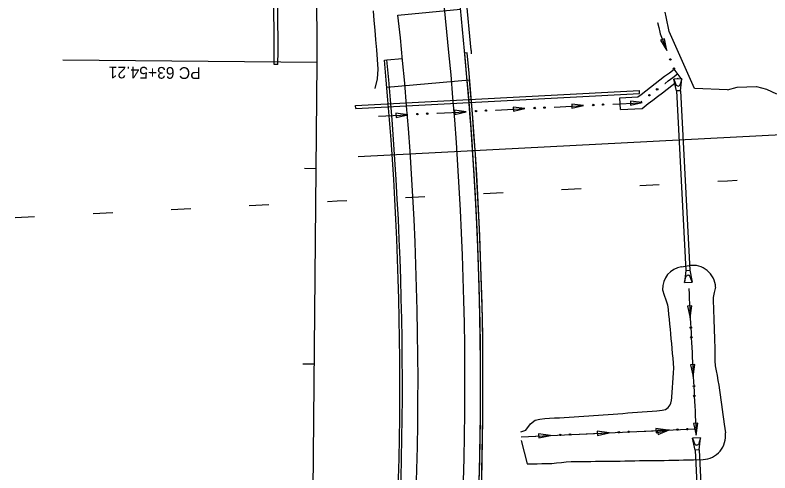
# Model space of a CAD drawing. Extents: x 1304554 to 1314558, y 2088110 to 2090513.
# Drawn here: x 1313845.5 to 1314231.7, y 2089262.8 to 2089497.1 of the extents above; entities that cross this region are included whole.
import ezdxf

# ---------------------------------------------------------------- set-up
doc = ezdxf.new("R2010")
doc.units = 0
for name, color, linetype in [('B-Sub-Retaining Wall', 7, 'Continuous'), ('MOT_Barrier Wall Stage 3', 7, 'Continuous'), ('R_Bridge', 7, 'Continuous'), ('R_Conc Ditch Paving', 7, 'Continuous'), ('R_Drainage', 7, 'Continuous'), ('R_Guardrail', 7, 'Continuous'), ('R_Horz Alg', 7, 'Continuous'), ('R_Horz Alg Annot', 7, 'Continuous'), ('R_Horz Alg Stationing', 7, 'Continuous'), ('R_Proposed Const Limits', 7, 'Continuous'), ('R_Proposed Road', 7, 'Continuous'), ('R_Shld_GR', 7, 'Continuous'), ('R_Shoulder', 7, 'Continuous'), ('R_Special Ditch', 7, 'Continuous'), ('S_Striping', 7, 'Continuous')]:
    doc.layers.add(name, color=color, linetype=linetype)

msp = doc.modelspace()

# ---------------------------------------------------------------- linework, layer by layer
at = {"layer": 'B-Sub-Retaining Wall'}
for p, q in [((1314019.78, 2089450.85), (1314165.01, 2089458.46)), ((1314019.85, 2089449.35), (1314165.09, 2089456.97)), ((1314165.09, 2089456.97), (1314165.01, 2089458.46)), ((1314166.39, 2089452.33), (1314160.35, 2089453.08)), ((1314160.35, 2089453.08), (1314160.45, 2089450.97)), ((1314160.45, 2089450.97), (1314166.39, 2089452.33)), ((1314019.85, 2089449.35), (1314019.78, 2089450.85)), ((1314076.4, 2089447.67), (1314070.35, 2089448.42)), ((1314070.35, 2089448.42), (1314070.46, 2089446.3)), ((1314106.4, 2089449.22), (1314100.35, 2089449.97)), ((1314100.35, 2089449.97), (1314100.46, 2089447.86)), ((1314100.46, 2089447.86), (1314106.4, 2089449.22)), ((1314136.39, 2089450.78), (1314130.35, 2089451.53)), ((1314130.35, 2089451.53), (1314130.46, 2089449.41)), ((1314130.46, 2089449.41), (1314136.39, 2089450.78)), ((1314046.4, 2089446.12), (1314040.35, 2089446.86)), ((1314040.35, 2089446.86), (1314040.46, 2089444.75)), ((1314040.46, 2089444.75), (1314046.4, 2089446.12)), ((1314070.46, 2089446.3), (1314076.4, 2089447.67))]:
    msp.add_line(p, q, dxfattribs=at)
for points in [[(1314178.06, 2089462.16), (1314179.69, 2089463.4), (1314182.1, 2089465.24), (1314184.51, 2089467.05)], [(1314178.03, 2089462.14), (1314178.06, 2089462.16)], [(1314151.41, 2089451.56), (1314165.24, 2089452.27), (1314166.15, 2089452.98)], [(1314091.38, 2089448.45), (1314091.42, 2089448.45)], [(1314091.42, 2089448.45), (1314106.4, 2089449.22)], [(1314121.38, 2089450), (1314121.41, 2089450)], [(1314121.41, 2089450), (1314136.39, 2089450.78)], [(1314151.37, 2089451.56), (1314151.41, 2089451.56)], [(1314031.42, 2089445.34), (1314046.4, 2089446.12)], [(1314061.38, 2089446.89), (1314061.42, 2089446.89)], [(1314061.42, 2089446.89), (1314076.4, 2089447.67)]]:
    msp.add_lwpolyline(points, dxfattribs=at)
for centre in [(1314174.05, 2089459.13), (1314170.09, 2089456.08), (1314081.4, 2089447.97), (1314086.4, 2089448.22), (1314111.39, 2089449.52), (1314116.4, 2089449.78), (1314141.39, 2089451.07), (1314146.39, 2089451.33), (1314051.4, 2089446.41), (1314056.4, 2089446.67)]:
    msp.add_circle(centre, 0.375, dxfattribs=at)
at = {"layer": 'MOT_Barrier Wall Stage 3'}
for p, q in [((1313978.01, 2089471.82), (1313978.03, 2089473.03)), ((1313980.01, 2089471.81), (1313978.01, 2089471.82)), ((1313980.01, 2089471.81), (1313980.02, 2089473.01))]:
    msp.add_line(p, q, dxfattribs=at)
for radius in [1123.92, 1125.92]:
    msp.add_arc((1312854.15, 2089482.84), radius, 359.5, 7, dxfattribs=at)
at = {"layer": 'R_Bridge'}
for p, q in [((1314076.83, 2089477.71), (1314075.59, 2089477.6)), ((1314034.49, 2089474.02), (1314035.74, 2089474.13)), ((1314078.11, 2089463.77), (1314035.77, 2089460.08)), ((1314078.11, 2089463.77), (1314035.77, 2089460.08))]:
    msp.add_line(p, q, dxfattribs=at)
for radius, start, end in [(1782.95, 354.7437, 5.46314), (1784.2, 354.74404, 5.4628), (1741.7, 354.73222, 5.47462), (1742.95, 354.73258, 5.47426), (1782.95, 355.19361, 5.01323), (1784.2, 355.19363, 5.01321)]:
    msp.add_arc((1312300.74, 2089307.86), radius, start, end, dxfattribs=at)
at = {"layer": 'R_Conc Ditch Paving'}
for p, q in [((1314186.31, 2089464.67), (1314182.71, 2089469.45)), ((1314155.02, 2089454.75), (1314164.15, 2089455.23)), ((1314155.33, 2089448.76), (1314155.02, 2089454.75)), ((1314155.33, 2089448.76), (1314166.34, 2089449.33))]:
    msp.add_line(p, q, dxfattribs=at)
for points in [[(1314164.15, 2089455.23), (1314165.81, 2089456.51), (1314168.22, 2089458.38), (1314170.64, 2089460.24), (1314173.05, 2089462.1), (1314175.46, 2089463.95), (1314177.87, 2089465.79), (1314180.29, 2089467.63), (1314182.71, 2089469.45)], [(1314186.08, 2089464.49), (1314186.31, 2089464.67)], [(1314166.34, 2089449.33), (1314169.49, 2089451.77), (1314171.9, 2089453.64), (1314174.3, 2089455.49), (1314176.7, 2089457.34), (1314179.1, 2089459.18), (1314181.51, 2089461.02), (1314183.1, 2089462.23)]]:
    msp.add_lwpolyline(points, dxfattribs=at)
at = {"layer": 'R_Drainage'}
for p, q in [((1314186.64, 2089464.52), (1314182.65, 2089464.31)), ((1314183.96, 2089458.25), (1314182.65, 2089464.31)), ((1314182.65, 2089464.31), (1314183.68, 2089461.56)), ((1314186.64, 2089464.52), (1314185.9, 2089461.68)), ((1314185.96, 2089458.36), (1314186.64, 2089464.52)), ((1314185.96, 2089458.36), (1314183.96, 2089458.25)), ((1314183.96, 2089458.25), (1314188.72, 2089366.38)), ((1314185.96, 2089458.36), (1314190.72, 2089366.48)), ((1314188.72, 2089366.38), (1314188.04, 2089360.21)), ((1314188.04, 2089360.21), (1314188.79, 2089363.06)), ((1314188.72, 2089366.38), (1314190.72, 2089366.48)), ((1314190.72, 2089366.48), (1314192.04, 2089360.42)), ((1314192.04, 2089360.42), (1314191, 2089363.17)), ((1314188.04, 2089360.21), (1314192.04, 2089360.42)), ((1314196.16, 2089280.77), (1314192.17, 2089280.56)), ((1314193.48, 2089274.5), (1314192.17, 2089280.56)), ((1314192.17, 2089280.56), (1314193.2, 2089277.81)), ((1314196.16, 2089280.77), (1314195.42, 2089277.93)), ((1314195.48, 2089274.6), (1314196.16, 2089280.77)), ((1314195.48, 2089274.6), (1314193.48, 2089274.5)), ((1314193.48, 2089274.5), (1314198.5, 2089177.63)), ((1314195.48, 2089274.6), (1314200.5, 2089177.73))]:
    msp.add_line(p, q, dxfattribs=at)
for centre, start, end in [((1314184.77, 2089461.97), 200.4966, 345.4367), ((1314189.91, 2089362.77), 20.4966, 165.4367), ((1314194.29, 2089278.21), 200.4966, 345.4367)]:
    msp.add_arc(centre, 1.17, start, end, dxfattribs=at)
at = {"layer": 'R_Guardrail'}
msp.add_arc((1312300.74, 2089307.86), 1782.95, 5.44344, 5.5, dxfattribs=at)
at = {"layer": 'R_Horz Alg'}
msp.add_line((1313996.9, 2089115.37), (1314000.02, 2089472.84), dxfattribs=at)
msp.add_line((1313996.9, 2089115.37), (1314000.02, 2089472.84), dxfattribs=at)
msp.add_arc((1312854.15, 2089482.84), 1145.92, 359.5, 7, dxfattribs=at)
msp.add_arc((1312854.15, 2089482.84), 1145.92, 359.5, 7, dxfattribs=at)
at = {"layer": 'R_Horz Alg Annot'}
msp.add_lwpolyline([(1314000.02, 2089472.84), (1313870.03, 2089473.97)], dxfattribs=at)
at = {"layer": 'R_Horz Alg Stationing'}
for points in [[(1313993.55, 2089418.69), (1313999.55, 2089418.63)], [(1313992.68, 2089318.69), (1313998.68, 2089318.64)]]:
    msp.add_lwpolyline(points, dxfattribs=at)
at = {"layer": 'R_Proposed Const Limits'}
for p, q in [((1314186.56, 2089368.33), (1314190.5, 2089368.91)), ((1314104.45, 2089281.32), (1314193.33, 2089285.33)), ((1314119.44, 2089282), (1314113.4, 2089282.78)), ((1314113.4, 2089282.78), (1314113.49, 2089280.67)), ((1314113.49, 2089280.67), (1314119.44, 2089282)), ((1314149.44, 2089283.35), (1314143.4, 2089284.14)), ((1314143.4, 2089284.14), (1314143.5, 2089282.02)), ((1314143.5, 2089282.02), (1314149.44, 2089283.35)), ((1314179.45, 2089284.71), (1314173.41, 2089285.49)), ((1314173.41, 2089285.49), (1314173.51, 2089283.38)), ((1314173.51, 2089283.38), (1314179.45, 2089284.71)), ((1314180.13, 2089284.86), (1314174.05, 2089284.58)), ((1314174.05, 2089284.58), (1314174.51, 2089282.52)), ((1314174.51, 2089282.52), (1314180.13, 2089284.86))]:
    msp.add_line(p, q, dxfattribs=at)
for points in [[(1314029.73, 2089459.56), (1314030.95, 2089464.51), (1314031.32, 2089469.49), (1314030.96, 2089474.41), (1314030.54, 2089479.39), (1314030.12, 2089484.37), (1314029.7, 2089489.36), (1314029.32, 2089494.34), (1314028.9, 2089499.33)], [(1314209.97, 2089458.77), (1314193.07, 2089459.52), (1314180.11, 2089488.77), (1314179.63, 2089491.24), (1314179.14, 2089493.7), (1314178.65, 2089496.17), (1314178.16, 2089498.63)], [(1314209.97, 2089458.77), (1314214.9, 2089460.21), (1314219.9, 2089460.35), (1314224.9, 2089460.5), (1314229.98, 2089459.13), (1314235.11, 2089456.77)], [(1314176.83, 2089356.47), (1314177.7, 2089353.79), (1314178.5, 2089351.33), (1314179.3, 2089348.87), (1314179.64, 2089346.38), (1314179.89, 2089343.89), (1314180.13, 2089341.4), (1314180.38, 2089338.91), (1314180.62, 2089336.42), (1314180.87, 2089333.93), (1314181.1, 2089331.44), (1314181.32, 2089328.94), (1314181.54, 2089326.45), (1314181.77, 2089323.96), (1314181.99, 2089321.47), (1314182.21, 2089318.98), (1314182.33, 2089316.48), (1314182.16, 2089313.97), (1314182, 2089311.46), (1314181.84, 2089308.94), (1314181.68, 2089306.43), (1314181.52, 2089303.92), (1314181.16, 2089299.43)], [(1314203.95, 2089357.88), (1314203.3, 2089355.12), (1314202.71, 2089352.58), (1314202.78, 2089350.08), (1314202.86, 2089347.58), (1314202.94, 2089345.09), (1314203.02, 2089342.59), (1314203.1, 2089340.09), (1314203.19, 2089337.59), (1314203.27, 2089335.09), (1314203.35, 2089332.59), (1314203.43, 2089330.09), (1314203.51, 2089327.59), (1314203.54, 2089325.09), (1314203.56, 2089322.59), (1314203.58, 2089320.08), (1314203.79, 2089317.59), (1314204.25, 2089315.11), (1314204.71, 2089312.63), (1314205.17, 2089310.15), (1314205.55, 2089307.67), (1314205.9, 2089305.18), (1314206.24, 2089302.7), (1314206.59, 2089300.21), (1314206.93, 2089297.73), (1314207.28, 2089295.24), (1314207.62, 2089292.76), (1314207.97, 2089290.27), (1314208.31, 2089287.79), (1314208.94, 2089283.3)], [(1314104.34, 2089283.89), (1314106.81, 2089284.62), (1314109.16, 2089287.92), (1314111.58, 2089289.83), (1314114.06, 2089290.28), (1314116.55, 2089290.62), (1314119.04, 2089290.85), (1314121.53, 2089290.96), (1314124.03, 2089291.06), (1314126.53, 2089291.17), (1314129.03, 2089291.27), (1314131.52, 2089291.43), (1314134.02, 2089291.59), (1314136.51, 2089291.75), (1314139.01, 2089291.92), (1314141.5, 2089292.14), (1314143.99, 2089292.37), (1314146.49, 2089292.56), (1314148.98, 2089292.72), (1314151.48, 2089292.88), (1314153.97, 2089293.05), (1314156.47, 2089293.26), (1314158.96, 2089293.49), (1314161.45, 2089293.69), (1314163.95, 2089293.85), (1314166.44, 2089294.02), (1314168.94, 2089294.18), (1314171.43, 2089294.39), (1314173.92, 2089294.62), (1314176.59, 2089294.84)], [(1314104.45, 2089281.32), (1314119.44, 2089282)], [(1314134.42, 2089282.67), (1314134.46, 2089282.68)], [(1314134.46, 2089282.68), (1314149.44, 2089283.35)], [(1314164.43, 2089284.03), (1314164.47, 2089284.03)], [(1314164.47, 2089284.03), (1314179.45, 2089284.71)], [(1314179.45, 2089284.71), (1314173.41, 2089285.49), (1314173.51, 2089283.38), (1314179.45, 2089284.71)], [(1314104.54, 2089279.32), (1314107.58, 2089267.36), (1314110.08, 2089267.45), (1314112.58, 2089267.5), (1314115.08, 2089267.56), (1314117.58, 2089267.62), (1314120.08, 2089267.67), (1314122.58, 2089267.89), (1314125.06, 2089268.2), (1314127.55, 2089268.52), (1314130.05, 2089268.59), (1314132.55, 2089268.58), (1314135.06, 2089268.58), (1314137.56, 2089268.63), (1314140.06, 2089268.68), (1314142.56, 2089268.74), (1314145.06, 2089268.79), (1314147.56, 2089268.84), (1314150.06, 2089268.83), (1314152.56, 2089268.82), (1314155.07, 2089268.86), (1314157.57, 2089268.91), (1314160.07, 2089268.96), (1314162.57, 2089269.02), (1314165.07, 2089269.07), (1314167.57, 2089269.11), (1314170.07, 2089269.11), (1314172.57, 2089269.11), (1314175.07, 2089269.16), (1314177.57, 2089269.22), (1314180.07, 2089269.27), (1314182.57, 2089269.33), (1314185.07, 2089269.38), (1314187.57, 2089269.42), (1314190.08, 2089269.42), (1314192.58, 2089269.45), (1314197.54, 2089269.65)]]:
    msp.add_lwpolyline(points, dxfattribs=at)
for centre in [(1314124.44, 2089282.26), (1314129.44, 2089282.49), (1314154.44, 2089283.61), (1314159.45, 2089283.84), (1314184.45, 2089284.97), (1314189.46, 2089285.19)]:
    msp.add_circle(centre, 0.375, dxfattribs=at)
for centre, radius, start, end in [((1314188.21, 2089357.06), 11.39, 98.299, 182.9667), ((1314192.2, 2089357.27), 11.76, 2.9667, 98.299), ((1314176.18, 2089299.82), 5, 274.7301, 355.424), ((1314197.05, 2089281.64), 12, 272.3118, 7.9083)]:
    msp.add_arc(centre, radius, start, end, dxfattribs=at)
at = {"layer": 'R_Proposed Road'}
for p, q in [((1314067.51, 2089477.98), (1314023.81, 2089931.84)), ((1314041.43, 2089497.1), (1314073.41, 2089500.18)), ((1314035.74, 2089474.13), (1314043.7, 2089474.89))]:
    msp.add_line(p, q, dxfattribs=at)
for radius, start, end in [(1750.95, 354.00707, 6.20458), (1774.95, 353.5625, 5.5), (1774.95, 353.5625, 5.5)]:
    msp.add_arc((1312300.74, 2089307.86), radius, start, end, dxfattribs=at)
at = {"layer": 'R_Shld_GR'}
msp.add_line((1314078.96, 2089479.08), (1314074.93, 2089520.9), dxfattribs=at)
msp.add_arc((1312300.74, 2089307.86), 1786.45, 5.44344, 5.5, dxfattribs=at)
at = {"layer": 'R_Shoulder'}
for p, q in [((1314075.48, 2089478.75), (1314031.77, 2089932.6)), ((1314021.14, 2089424.78), (1314480.86, 2089448.61))]:
    msp.add_line(p, q, dxfattribs=at)
msp.add_arc((1312300.74, 2089307.86), 1782.95, 353.5625, 5.5, dxfattribs=at)
at = {"layer": 'R_Special Ditch'}
for p, q in [((1314177.77, 2089485.01), (1314175.8, 2089484.24)), ((1314175.8, 2089484.24), (1314178.96, 2089479.03)), ((1314178.96, 2089479.03), (1314177.77, 2089485.01)), ((1314191.72, 2089348.23), (1314189.61, 2089348.12)), ((1314189.61, 2089348.12), (1314190.98, 2089342.18)), ((1314190.98, 2089342.18), (1314191.72, 2089348.23)), ((1314193.28, 2089318.23), (1314191.17, 2089318.12)), ((1314191.17, 2089318.12), (1314192.53, 2089312.19)), ((1314192.53, 2089312.19), (1314193.28, 2089318.23)), ((1314194.83, 2089288.23), (1314192.72, 2089288.13)), ((1314192.72, 2089288.13), (1314194.09, 2089282.19)), ((1314194.09, 2089282.19), (1314194.83, 2089288.23))]:
    msp.add_line(p, q, dxfattribs=at)
for points in [[(1314174.25, 2089493.28), (1314174.26, 2089493.24)], [(1314174.26, 2089493.24), (1314174.26, 2089493.23), (1314174.86, 2089490.78), (1314175.46, 2089488.32), (1314175.65, 2089487.54), (1314178.96, 2089479.03)], [(1314184.4, 2089465.05), (1314184.41, 2089465.02)], [(1314184.41, 2089465.01), (1314184.64, 2089464.42)], [(1314190.2, 2089357.16), (1314190.21, 2089356.94), (1314190.34, 2089354.45), (1314190.47, 2089351.95), (1314190.6, 2089349.45), (1314190.73, 2089346.96), (1314190.86, 2089344.46), (1314190.99, 2089341.96), (1314191.12, 2089339.47), (1314191.25, 2089336.97), (1314191.38, 2089334.47), (1314191.51, 2089331.98), (1314191.64, 2089329.48), (1314191.77, 2089326.98), (1314191.9, 2089324.49), (1314192.03, 2089321.99), (1314192.15, 2089319.49), (1314192.28, 2089317), (1314192.41, 2089314.5), (1314192.54, 2089312), (1314192.67, 2089309.51), (1314192.8, 2089307.01), (1314192.93, 2089304.51), (1314193.06, 2089302.02), (1314193.19, 2089299.52), (1314193.32, 2089297.02), (1314193.45, 2089294.53), (1314193.58, 2089292.03), (1314193.71, 2089289.53), (1314193.84, 2089287.04), (1314193.97, 2089284.54), (1314194.03, 2089283.37)], [(1314190.2, 2089357.16), (1314190.21, 2089356.94), (1314190.34, 2089354.45), (1314190.47, 2089351.95), (1314190.6, 2089349.45), (1314190.73, 2089346.96), (1314190.86, 2089344.46), (1314190.98, 2089342.18)], [(1314191.75, 2089327.2), (1314191.76, 2089327.17)], [(1314191.76, 2089327.17), (1314191.77, 2089326.98), (1314191.9, 2089324.49), (1314192.03, 2089321.99), (1314192.15, 2089319.49), (1314192.28, 2089317), (1314192.41, 2089314.5), (1314192.53, 2089312.19)], [(1314193.31, 2089297.21), (1314193.31, 2089297.17)], [(1314193.31, 2089297.17), (1314193.32, 2089297.02), (1314193.45, 2089294.53), (1314193.58, 2089292.03), (1314193.71, 2089289.53), (1314193.84, 2089287.04), (1314193.97, 2089284.54), (1314194.03, 2089283.37)]]:
    msp.add_lwpolyline(points, dxfattribs=at)
for centre in [(1314180.81, 2089474.38), (1314182.62, 2089469.71), (1314191.27, 2089337.19), (1314191.53, 2089332.18), (1314192.83, 2089307.19), (1314193.09, 2089302.18)]:
    msp.add_circle(centre, 0.375, dxfattribs=at)
at = {"layer": 'S_Striping'}
for p, q in [((1314165.11, 2089409.94), (1314175.1, 2089410.46)), ((1314085.22, 2089405.84), (1314095.2, 2089406.35)), ((1314045.27, 2089403.78), (1314055.26, 2089404.29)), ((1313965.38, 2089399.66), (1313975.36, 2089400.17)), ((1313845.53, 2089393.51), (1313855.52, 2089394.01)), ((1313885.48, 2089395.54), (1313895.47, 2089396.05))]:
    msp.add_line(p, q, dxfattribs=at)
for points in [[(1314205.06, 2089412.03), (1314210.05, 2089412.29), (1314215.04, 2089412.55)], [(1314125.16, 2089407.87), (1314135.15, 2089408.38), (1314135.15, 2089408.38)], [(1314005.32, 2089401.72), (1314010.31, 2089401.97), (1314015.31, 2089402.23)], [(1313925.43, 2089397.61), (1313935.41, 2089398.13), (1313935.41, 2089398.13)]]:
    msp.add_lwpolyline(points, dxfattribs=at)

# ---------------------------------------------------------------- texts
at = {"layer": 'R_Horz Alg Annot'}
msp.add_text('PC 63+54.21', height=6, rotation=179.5, dxfattribs=at).set_placement((1313940.5, 2089470.36))

doc.saveas('drawing.dxf')
